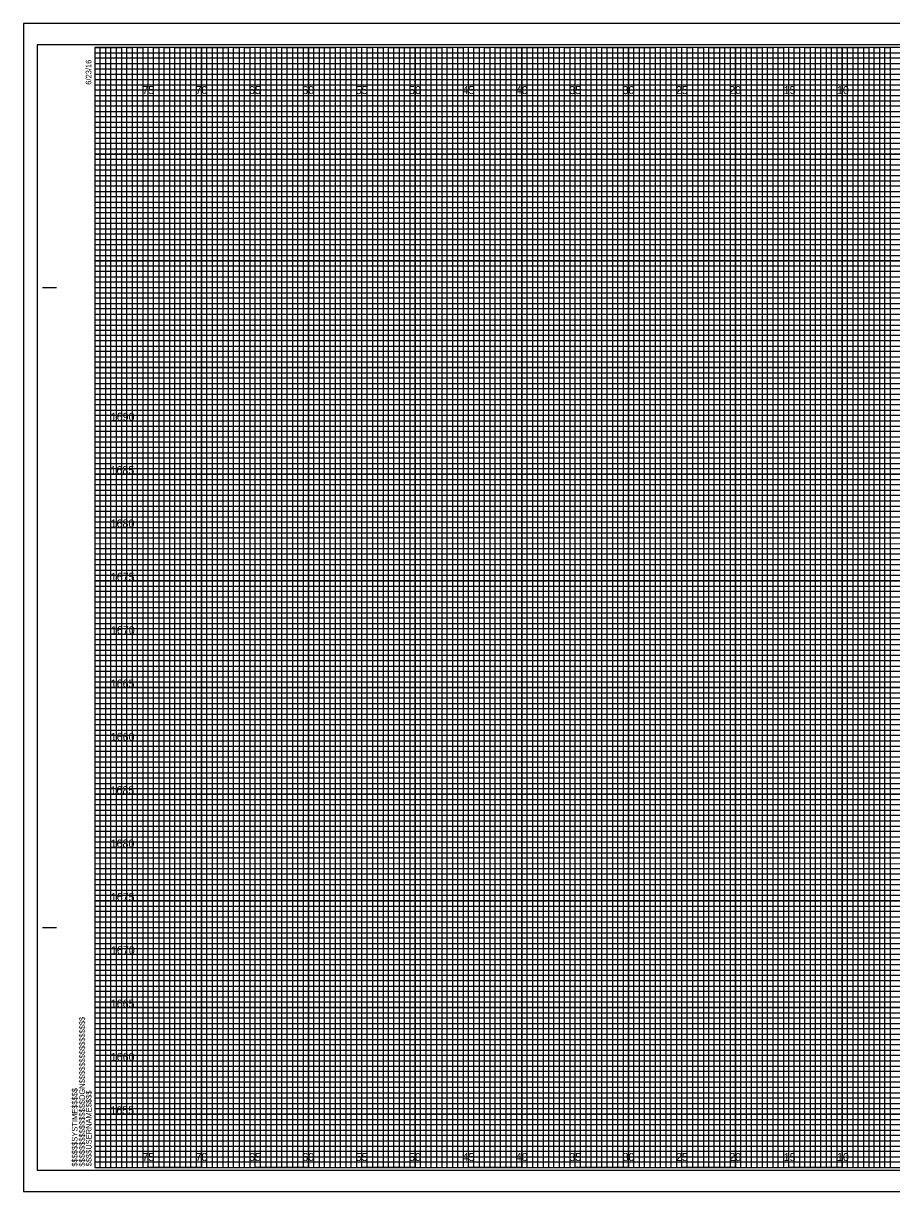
# Model space of a CAD drawing. Extents: x -7 to 162, y -2 to 107.
# Drawn here: x -6.7 to 74.6, y -2.3 to 107.3 of the extents above; entities that cross this region are included whole.
import ezdxf

# ---------------------------------------------------------------- set-up
doc = ezdxf.new("R2010")
doc.units = 0
for name, color, linetype in [('Raster_Level_0', 7, 'Continuous'), ('Scratch_Level_3', 7, 'Continuous'), ('Sheet Cross Section CELL', 7, 'Continuous'), ('Sheet Cross Section Grid Major CELL', 7, 'Continuous'), ('Sheet Cross Section Grid Middle CELL', 7, 'Continuous'), ('Sheet Cross Section Grid Minor 1 CELL', 7, 'Continuous'), ('Sheet Cross Section Grid Minor 2 CELL', 7, 'Continuous'), ('Sheet Cutting Line CELL', 7, 'Continuous'), ('Sheet DOT Grid CELL', 7, 'Continuous'), ('Sheet Plot Border Inside CELL', 7, 'Continuous'), ('Sheet Plot Border Outside CELL', 7, 'Continuous')]:
    doc.layers.add(name, color=color, linetype=linetype)

msp = doc.modelspace()

# ---------------------------------------------------------------- linework, layer by layer
at = {"layer": 'Sheet Cross Section CELL'}
for p, q in [((-4.9, 82.5), (-3.65, 82.5)), ((-4.85, 82.5), (-3.6, 82.5)), ((-4.9, 22.5), (-3.65, 22.5)), ((-4.85, 22.5), (-3.6, 22.5)), ((0, 0), (0, 0)), ((0, 0), (0, 0)), ((0, 0), (0, 0)), ((0, 0), (0, 0)), ((0, 0), (0, 0)), ((0, 0), (0, 0)), ((0, 0), (0, 0))]:
    msp.add_line(p, q, dxfattribs=at)
msp.add_lwpolyline([(160, 105), (0, 105), (0, 0), (160, 0)], close=True, dxfattribs=at)
at = {"layer": 'Sheet Cross Section Grid Major CELL'}
for p, q in [((5, 105), (0, 105)), ((5, 0), (5, 105)), ((15, 105), (10, 105)), ((10, 105), (10, 0)), ((15, 0), (15, 105)), ((25, 105), (20, 105)), ((20, 105), (20, 0)), ((25, 0), (25, 105)), ((35, 105), (30, 105)), ((30, 105), (30, 0)), ((35, 0), (35, 105)), ((45, 105), (40, 105)), ((40, 105), (40, 0)), ((45, 0), (45, 105)), ((55, 105), (50, 105)), ((50, 105), (50, 0)), ((55, 0), (55, 105)), ((65, 105), (60, 105)), ((60, 105), (60, 0)), ((65, 0), (65, 105)), ((75, 105), (70, 105)), ((70, 105), (70, 0)), ((10, 0), (5, 0)), ((20, 0), (15, 0)), ((30, 0), (25, 0)), ((40, 0), (35, 0)), ((50, 0), (45, 0)), ((60, 0), (55, 0)), ((70, 0), (65, 0))]:
    msp.add_line(p, q, dxfattribs=at)
for points in [[(0, 100), (160, 100), (160, 95), (0, 95)], [(0, 90), (160, 90), (160, 85), (0, 85)], [(0, 80), (160, 80), (160, 75), (0, 75)], [(0, 70), (160, 70), (160, 65), (0, 65)], [(0, 60), (160, 60), (160, 55), (0, 55)], [(0, 50), (160, 50), (160, 45), (0, 45)], [(0, 40), (160, 40), (160, 35), (0, 35)], [(0, 30), (160, 30), (160, 25), (0, 25)], [(0, 20), (160, 20), (160, 15), (0, 15)], [(0, 10), (160, 10), (160, 5), (0, 5)]]:
    msp.add_lwpolyline(points, dxfattribs=at)
at = {"layer": 'Sheet Cross Section Grid Middle CELL'}
for points in [[(0, 105), (2.5, 105), (2.5, 0), (7.5, 0), (7.5, 105), (12.5, 105), (12.5, 0), (17.5, 0), (17.5, 105), (22.5, 105), (22.5, 0), (27.5, 0), (27.5, 105), (32.5, 105), (32.5, 0), (37.5, 0), (37.5, 105), (42.5, 105), (42.5, 0), (47.5, 0), (47.5, 105), (52.5, 105), (52.5, 0), (57.5, 0), (57.5, 105), (62.5, 105), (62.5, 0), (67.5, 0), (67.5, 105), (72.5, 105), (72.5, 0), (77.5, 0)], [(0, 102.5), (137.5, 102.5)], [(0, 92.5), (160, 92.5), (160, 97.5), (0, 97.5)], [(0, 82.5), (160, 82.5), (160, 87.5), (0, 87.5)], [(0, 72.5), (160, 72.5), (160, 77.5), (0, 77.5)], [(0, 62.5), (160, 62.5), (160, 67.5), (0, 67.5)], [(0, 52.5), (160, 52.5), (160, 57.5), (0, 57.5)], [(0, 42.5), (160, 42.5), (160, 47.5), (0, 47.5)], [(0, 32.5), (160, 32.5), (160, 37.5), (0, 37.5)], [(0, 22.5), (160, 22.5), (160, 27.5), (0, 27.5)], [(0, 12.5), (160, 12.5), (160, 17.5), (0, 17.5)], [(0, 2.5), (160, 2.5), (160, 7.5), (0, 7.5)]]:
    msp.add_lwpolyline(points, dxfattribs=at)
at = {"layer": 'Sheet Cross Section Grid Minor 1 CELL'}
for p, q in [((0, 104.5), (130, 104.5)), ((130, 103.99), (0, 103.99)), ((0, 103.99), (0, 103.5)), ((0, 103.5), (130, 103.5)), ((130, 102.95), (0, 102.95)), ((0, 102.95), (0, 102)), ((0, 102), (160, 102))]:
    msp.add_line(p, q, dxfattribs=at)
for points in [[(0, 101.5), (135, 101.5), (160, 101.5), (160, 101), (0, 101)], [(0, 100.5), (160, 100.5), (160, 99.5), (0, 99.5)], [(0, 99), (160, 99), (160, 98.5), (0, 98.49)], [(0, 98), (160, 98), (160, 97), (0, 97)], [(0, 96.5), (160, 96.5), (160, 96), (0, 96)], [(0, 95.5), (160, 95.5), (160, 94.5), (0, 94.5)], [(0, 94), (160, 94), (160, 93.5), (0, 93.5)], [(0, 93), (160, 93), (160, 92), (0, 92)], [(0, 91.5), (160, 91.5), (160, 91), (0, 91)], [(0, 90.5), (160, 90.5), (160, 89.5), (0, 89.5)], [(0, 89), (160, 89), (160, 88.5), (0, 88.5)], [(0, 88), (160, 88), (160, 86.98), (160, 86.5), (160, 86), (0, 86)], [(0, 87), (160, 87), (160, 86.5), (0, 86.5)], [(0, 85.5), (160, 85.5), (160, 84.5), (0, 84.52)], [(0, 84.52), (160, 84.5), (160, 84), (0, 84)], [(0, 83.5), (160, 83.5), (160, 83), (0, 83)], [(0, 82), (160, 82), (160, 81.5), (0, 81.5)], [(0, 81), (160, 81), (160, 80.5), (0, 80.5)], [(-0.04, 79.45), (160, 79.45), (160, 78.94), (-0.04, 78.94)], [(0, 78.5), (160, 78.5), (160, 78), (0, 78)], [(0, 77), (160, 77), (160, 76.5), (0, 76.5)], [(0, 76), (160, 76), (160, 75.5), (0, 75.5)], [(0, 74.5), (160, 74.5), (160, 74), (0, 74)], [(0, 73.5), (160, 73.5), (160, 73), (0, 73)], [(0, 72), (160, 72), (160, 71.5), (0, 71.5)], [(0, 71), (160, 71), (160, 70.5), (0, 70.5)], [(0, 69.5), (160, 69.5), (160, 68.99), (0, 69)], [(0, 68.5), (160, 68.5), (160, 68), (0, 68)], [(0, 67), (160, 67), (160, 66.5), (0, 66.5)], [(0, 66), (160, 66), (160, 65.5), (0, 65.5)], [(0, 64.5), (160, 64.5), (160, 64), (0, 64)], [(0, 63.5), (160, 63.5), (160, 63), (0, 63)], [(0, 62), (160, 62), (160, 61.5), (0, 61.5)], [(0, 61), (160, 61), (160, 60.5), (0, 60.5)], [(0, 59.5), (160, 59.5), (160, 59), (0, 59)], [(0, 58.5), (160.03, 58.45), (160, 58), (0, 58)], [(0, 57), (160, 57), (160, 56.5), (0, 56.5)], [(0, 56), (160, 56), (160, 55.5), (0, 55.5)], [(0, 54.5), (160, 54.5), (160, 54), (0, 54)], [(0, 53.5), (160, 53.5), (160, 53), (0, 53)], [(0, 52), (160, 52), (160, 51.5), (0, 51.5)], [(0, 51), (160, 51), (160, 50.5), (0, 50.5)], [(0, 49.5), (160, 49.5), (160, 49), (0, 49)], [(0, 48.5), (160, 48.5), (160, 48), (0, 48)], [(0, 47), (160, 47), (160, 46.5), (0, 46.5)], [(0, 46), (160, 46), (160, 45.5), (0, 45.5)], [(0, 44.5), (160, 44.5), (160, 44), (0, 44)], [(0, 43.5), (160, 43.5), (160, 43), (0, 43)], [(0, 42), (160, 42), (160, 41.5), (0, 41.5)], [(0, 41), (160, 41), (160, 40.5), (0, 40.5)], [(0, 39.5), (160, 39.5), (160, 38.99), (0, 39)], [(0, 38.5), (160, 38.5), (160, 38), (0, 38)], [(0, 37), (160, 37), (160, 36.5), (0, 36.5)], [(0, 36), (160, 36), (160, 35.5), (0, 35.5)], [(0, 34.5), (160, 34.5), (160, 34), (0, 34)], [(0, 33.5), (160, 33.5), (160, 33), (0, 33)], [(0, 32), (160, 32), (160, 31.5), (0, 31.5)], [(0, 31), (160, 31), (160, 30.5), (0, 30.5)], [(0, 29.5), (160, 29.5), (160, 29), (0, 29)], [(0, 28.5), (160.03, 28.46), (160, 28), (0, 28)], [(0, 27), (160, 27), (160, 26.5), (0, 26.5)], [(0, 26), (160, 26), (160, 25.5), (0, 25.5)], [(0, 24.5), (160, 24.5), (160, 24), (0, 24)], [(0, 23.5), (160, 23.5), (160, 23), (0, 23)], [(0, 22), (160, 22), (160, 21.5), (0, 21.5)], [(0, 21), (160, 21), (160, 20.5), (0, 20.5)], [(0, 19.5), (160, 19.5), (160, 19), (0, 19)], [(0, 18.5), (160, 18.5), (160, 18), (0, 18)], [(0, 17), (160, 17), (160, 16.5), (0, 16.5)], [(0, 16), (160, 16), (160, 15.5), (0, 15.5)], [(0, 14.5), (160, 14.5), (160, 14), (0, 14)], [(0, 13.5), (160, 13.5), (160, 13), (0, 13)], [(0, 12), (160, 12), (160, 11.5), (0, 11.5)], [(0, 11), (160, 11), (160, 10.5), (0, 10.5)], [(0, 9.5), (160, 9.5), (160, 9), (0, 9)], [(0, 8.5), (160, 8.5), (160, 8), (0, 8)], [(0, 7), (160, 7), (160, 6.5), (0, 6.5)], [(0, 6), (160, 6), (160, 5.5), (0, 5.5)], [(0, 4.5), (160, 4.5), (160, 4), (0, 4)], [(0, 3.5), (160, 3.5), (160, 3), (0, 3)], [(0, 2), (160, 2), (160, 1.5), (0, 1.5)], [(0, 1), (160, 1), (160, 0.5), (0, 0.5)]]:
    msp.add_lwpolyline(points, dxfattribs=at)
at = {"layer": 'Sheet Cross Section Grid Minor 2 CELL'}
for points in [[(0, 0), (0.5, 0), (0.5, 105), (1, 105), (1, 0)], [(1, 0), (1.5, 0), (1.5, 105), (2, 105), (2, 0)], [(2.5, 0), (3, 0), (3, 105), (3.5, 105), (3.5, 0)], [(3.5, 0), (4, 0), (4, 105), (4.5, 105), (4.5, 0)], [(5, 0), (5.5, 0), (5.5, 105), (6, 105), (6, 0)], [(6, 0), (6.5, 0), (6.5, 105), (7, 105), (7, 0)], [(7.5, 0), (8, 0), (8, 105), (8.5, 105), (8.5, 0)], [(8.5, 0), (9, 0), (9, 105), (9.5, 105), (9.5, 0)], [(10, 0), (10.5, 0), (10.5, 105), (11, 105), (11, 0)], [(11, 0), (11.5, 0), (11.5, 105), (12, 105), (12, 0)], [(12.5, 0), (13, 0), (13, 105), (13.5, 105), (13.5, 0)], [(13.5, 0), (14, 0), (14, 105), (14.5, 105), (14.5, 0)], [(15, 0), (15.5, 0), (15.5, 105), (16, 105), (16, 0)], [(16, 0), (16.5, 0), (16.5, 105), (17, 105), (17, 0)], [(17.5, 0), (18, 0), (18, 105), (18.5, 105), (18.5, 0)], [(18.5, 0), (19, 0), (19, 105), (19.5, 105), (19.5, 0)], [(20, 0), (20.5, 0), (20.5, 105), (21, 105), (21, 0)], [(21, 0), (21.5, 0), (21.5, 105), (22, 105), (22, 0)], [(22.5, 0), (23, 0), (23, 105), (23.5, 105), (23.5, 0)], [(23.5, 0), (24, 0), (24, 105), (24.5, 105), (24.5, 0)], [(25, 0), (25.5, 0), (25.5, 105), (26, 105), (26, 0)], [(26, 0), (26.5, 0), (26.5, 105), (27, 105), (27, 0)], [(27.5, 0), (28, 0), (28, 105), (28.5, 105), (28.5, 0)], [(28.5, 0), (29, 0), (29, 105), (29.5, 105), (29.5, 0)], [(30, 0), (30.5, 0), (30.5, 105), (31, 105), (31, 0)], [(31, 0), (31.5, 0), (31.5, 105), (32, 105), (32, 0)], [(32.5, 0), (33, 0), (33, 105), (33.5, 105), (33.5, 0)], [(33.5, 0), (34, 0), (34, 105), (34.5, 105), (34.5, 0)], [(35, 0), (35.5, 0), (35.5, 105), (36, 105), (36, 0)], [(36, 0), (36.5, 0), (36.5, 105), (37, 105), (37, 0)], [(37.5, 0), (38, 0), (38, 105), (38.5, 105), (38.5, 0)], [(38.5, 0), (39, 0), (39, 105), (39.5, 105), (39.5, 0)], [(40, 0), (40.5, 0), (40.5, 105), (41, 105), (41, 0)], [(41, 0), (41.5, 0), (41.5, 105), (42, 105), (42, 0)], [(42.5, 0), (43, 0), (43, 105), (43.5, 105), (43.5, 0)], [(43.5, 0), (44, 0), (44, 105), (44.5, 105), (44.5, 0)], [(45, 0), (45.5, 0), (45.5, 105), (46, 105), (46, 0)], [(46, 0), (46.5, 0), (46.5, 105), (47, 105), (47, 0)], [(47.5, 0), (48, 0), (48, 105), (48.5, 105), (48.5, 0)], [(48.5, 0), (49, 0), (49, 105), (49.5, 105), (49.5, 0)], [(50, 0), (50.5, 0), (50.5, 105), (51, 105), (51, 0)], [(51, 0), (51.5, 0), (51.5, 105), (52, 105), (52, 0)], [(52.5, 0), (53, 0), (53, 105), (53.5, 105), (53.5, 0)], [(53.5, 0), (54, 0), (54, 105), (54.5, 105), (54.5, 0)], [(55, 0), (55.5, 0), (55.5, 105), (56, 105), (56, 0)], [(56, 0), (56.5, 0), (56.5, 105), (57, 105), (57, 0)], [(57.5, 0), (58, 0), (58, 105), (58.5, 105), (58.5, 0)], [(58.5, 0), (59, 0), (59, 105), (59.5, 105), (59.5, 0)], [(60, 0), (60.5, 0), (60.5, 105), (61, 105), (61, 0)], [(61, 0), (61.5, 0), (61.5, 105), (62, 105), (62, 0)], [(62.5, 0), (63, 0), (63, 105), (63.5, 105), (63.5, 0)], [(63.5, 0), (64, 0), (64, 105), (64.5, 105), (64.5, 0)], [(65, 0), (65.5, 0), (65.5, 105), (66, 105), (66, 0)], [(66, 0), (66.5, 0), (66.5, 105), (67, 105), (67, 0)], [(67.5, 0), (68, 0), (68, 105), (68.5, 105), (68.5, 0)], [(68.5, 0), (69, 0), (69, 105), (69.5, 105), (69.5, 0)], [(70, 0), (70.5, 0), (70.5, 105), (71, 105), (71, 0)], [(71, 0), (71.5, 0), (71.5, 105), (72, 105), (72, 0)], [(72.5, 0), (73, 0), (73, 105), (73.5, 105), (73.5, 0)], [(73.5, 0), (74, 0), (74, 105), (74.5, 105), (74.5, 0)]]:
    msp.add_lwpolyline(points, dxfattribs=at)
at = {"layer": 'Sheet Cutting Line CELL'}
for p, q in [((161.65, 107.25), (-6.7, 107.25)), ((-6.7, 107.25), (-6.7, -2.25)), ((-6.7, -2.25), (161.65, -2.25))]:
    msp.add_line(p, q, dxfattribs=at)
at = {"layer": 'Sheet DOT Grid CELL'}
for p, q in [((5, 0), (5, 105)), ((10, 0), (10, 105)), ((15, 0), (15, 105)), ((20, 0), (20, 105)), ((25, 0), (25, 105)), ((30, 0), (30, 105)), ((35, 0), (35, 105)), ((40, 0), (40, 105)), ((45, 0), (45, 105)), ((50, 0), (50, 105)), ((55, 0), (55, 105)), ((60, 0), (60, 105)), ((65, 0), (65, 105)), ((70, 0), (70, 105)), ((0, 100), (160, 100)), ((0, 95), (160, 95)), ((0, 90), (160, 90)), ((0, 85), (160, 85)), ((0, 80), (160, 80)), ((0, 75), (160, 75)), ((0, 70), (160, 70)), ((0, 65), (160, 65)), ((0, 60), (160, 60)), ((0, 55), (160, 55)), ((0, 50), (160, 50)), ((0, 45), (160, 45)), ((0, 40), (160, 40)), ((0, 35), (160, 35)), ((0, 30), (160, 30)), ((0, 25), (160, 25)), ((0, 20), (160, 20)), ((0, 15), (160, 15)), ((0, 10), (160, 10)), ((0, 5), (160, 5))]:
    msp.add_line(p, q, dxfattribs=at)
at = {"layer": 'Sheet Plot Border Inside CELL'}
msp.add_lwpolyline([(-5.4, -0.25), (161.2, -0.25), (161.2, 105.25), (-5.4, 105.25)], close=True, dxfattribs=at)
at = {"layer": 'Sheet Plot Border Outside CELL'}
msp.add_lwpolyline([(-6.7, -2.25), (161.65, -2.25), (161.65, 107.25), (-6.7, 107.25)], close=True, dxfattribs=at)

# ---------------------------------------------------------------- texts
at = {"layer": 'Raster_Level_0'}
for s, p in [('75', (4.44, 100.62)), ('70', (9.43, 100.62)), ('65', (14.44, 100.62)), ('60', (19.43, 100.62)), ('55', (24.44, 100.62)), ('50', (29.43, 100.62)), ('45', (34.44, 100.62)), ('40', (39.43, 100.62)), ('35', (44.44, 100.62)), ('30', (49.43, 100.62)), ('25', (54.44, 100.62)), ('20', (59.43, 100.62)), ('15', (64.53, 100.62)), ('10', (69.52, 100.62)), ('75', (4.44, 0.62)), ('70', (9.43, 0.62)), ('65', (14.44, 0.62)), ('60', (19.43, 0.62)), ('55', (24.44, 0.62)), ('50', (29.43, 0.62)), ('45', (34.44, 0.62)), ('40', (39.43, 0.62)), ('35', (44.44, 0.62)), ('30', (49.43, 0.62)), ('25', (54.44, 0.62)), ('20', (59.43, 0.62)), ('15', (64.53, 0.62)), ('10', (69.52, 0.62))]:
    msp.add_text(s, height=0.75, dxfattribs=at).set_placement(p)
at = {"layer": 'Scratch_Level_3'}
for s, p in [('1690', (1.48, 70)), ('1685', (1.46, 65)), ('1680', (1.47, 60)), ('1675', (1.49, 55)), ('1670', (1.5, 50)), ('1665', (1.48, 45)), ('1660', (1.48, 40)), ('1685', (1.46, 35)), ('1680', (1.47, 30)), ('1675', (1.49, 25)), ('1670', (1.5, 20)), ('1665', (1.48, 15)), ('1660', (1.48, 10)), ('1655', (1.45, 5))]:
    msp.add_text(s, height=0.75, dxfattribs=at).set_placement(p)
at = {"layer": 'Sheet Cross Section CELL'}
for s, p in [('6/23/16', (-0.33, 101.5)), ('$$$$$$$$$$$$$$$$DGN$$$$$$$$$$$$$$$$', (-0.94, 0.09)), ('$$$$$$SYSTIME$$$$$', (-1.63, 0.09)), ('$$$$USERNAME$$$$', (-0.31, 0.12))]:
    msp.add_text(s, height=0.525, rotation=90, dxfattribs=at).set_placement(p)

doc.saveas('drawing.dxf')
